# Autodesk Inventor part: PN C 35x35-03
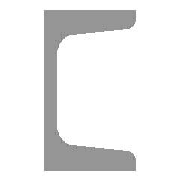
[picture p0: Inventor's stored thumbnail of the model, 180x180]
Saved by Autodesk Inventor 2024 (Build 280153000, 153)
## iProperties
Company: ATC
IsCustomPart: 1
Created: 2023-03
Part Number: PN C 35x35-03
Material: Ogólny
Description: Ceownik
Document SubType Name: Modeling
Standard: PN-86/H-93403
Designer: Andrzej Jaskulski
Standards Organization: PN
Language: pl-PL
Size Designation: C 35x35
Categories: <MemberInstance><Categories><Category DisplayName="Kształtowniki konstrukcyjne" InternalName="089c4875-fa83-4c05-b084-43b9cc11f5ed" Mnemonic="GRDR"><CategoryPar
Stock Number: C 35x35
Density: 1 g/cm^3
Appearance: Domyślna
Checked By: A.J.
Engr Approved By: Andrzej Jaskulski
Mfg Approved By: Andrzej Jaskulski
Authority: A.J.
_CCFamilyMember: 10
_CCFamilyDisplayName: PN-86/H-93403 - Ceownik
_FrameMemberDoc: Frame Member File
_Version: 15.0.0
G_L: 160,000 mm
G_W: 35,000 mm
G_H: 35,000 mm
+302763FE-E428-4782-AB0C-9204278D63AD+CUTDETAIL1: Połączenie narożne
Author: Andrzej Jaskulski
Title: A.J.: Kurs R2024-MEP
Revision Number: 1/24
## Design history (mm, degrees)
node "Płaszczyzna początkowa"
node "Płaszczyzna końcowa"
sketch "Szkic"
  geometry: L1 (0, 0)-(0, 17.5); L2 (0, 17.5)-(35, 17.5); L3 (35, 17.5)-(35, 15.47); L4 (32.239, 12.479)-(10.522, 10.742); L5 (5, 4.761)-(5, 0); L6 (5, 0)-(0, 0); L7 (20, 17.5)-(20, 11.5); L8 (35, 12.7)-(35, 11.5); L9 (35, 11.5)-(20, 11.5); L10 (0, 15)-(0, -27); L11 (-5.539, 0)-(16.007, 0); L12 (0, 0)-(0, -17.5); L13 (0, -17.5)-(35, -17.5); L14 (35, -17.5)-(35, -15.47); L15 (32.239, -12.479)-(10.522, -10.742); L16 (5, -4.761)-(5, 0); L17 (0, 26.4)-(0, -35.9) reference; L18 (-13.764, 0)-(43.809, 0) reference; A1 r 6 centre (11, 4.761) between (10.522, 10.742) and (5, 4.761); A2 r 6 centre (11, -4.761) between (5, -4.761) and (10.522, -10.742); A3 r 3 centre (32, 15.47) between (32.239, 12.479) and (35, 15.47); A4 r 3 centre (32, -15.47) between (35, -15.47) and (32.239, -12.479); 5 further points
  constraints: 32 end point, 12 point on line, 8 point on circle, 8 tangent, 6 symmetric about line, 4 centre point, 4 parallel, 3 collinear, 3 perpendicular, 2 equal radius, 5 other
  dimensions: "d0" = 5 distance between parallel lines of L1 L5 (= G_T); "d1" = 17.5 distance between parallel lines of L6 L2 (= 0.5 x G_H); "d2" = 35 distance between parallel lines of L3 L1 (= G_W); "d3" = 6 distance of L2.end L8.end (= G_T1); "d4" = 15 distance of L7.start L2.end (= G_C); "d5" = 1.2 distance of L8.start L8.end (computed from G_NG, G_C); "d23" = 6 radius of A1 (= G_IR); "d24" = 3 radius of A3 (= G_ER); "d25" = 0 distance between parallel lines of L10 L12 (computed from ex)
extrude "Bryła" new body sketch "Szkic" stored distance "d6" = 160 (= G_L); taper "d7" = 0 deg
node "Driven Length"
  sketch "Sketch3"
    geometry: L1 (0, 0)-(10, 0) reference
    constraints: 2 end point, 1 horizontal
  workplane "Work Plane3"
node "Płaszczyzna konstrukcyjna4"
feature "Podział1"
body "Solid1"
sketch "Sketch4"
  geometry: L1 (-2, 0)-(12, 0) reference; L2 (-2, 160)-(12, 160) reference
  dimensions: "d29" = 160 distance between parallel lines of L1 L2 (derived)
other parameters: "G_W" = 35 [user parameter; used in 1 equation term], "G_H" = 35 [user parameter; used in 1 equation term], "G_T" = 5 [user parameter; used in 1 equation term], "G_T1" = 6 [user parameter; used in 1 equation term], "G_NG" = 0.8 [user parameter; used in 1 equation term], "G_ER" = 3 [user parameter; used in 1 equation term], "G_IR" = 6 [user parameter; used in 1 equation term], "G_C" = 15 [user parameter; used in 2 equation terms], "G_L" = 160 (= d29) [user parameter; used in 1 equation term], "ex" = 0 [user parameter; used in 1 equation term], "G_OFFSET_START" = 0 [user parameter; used in 1 equation term], "d26" = 0 (computed from G_OFFSET_START), "d28" = 90 deg
